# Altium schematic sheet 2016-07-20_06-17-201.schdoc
size 265 x 111 mm; SheetNumber: 1; SheetTotal: 1
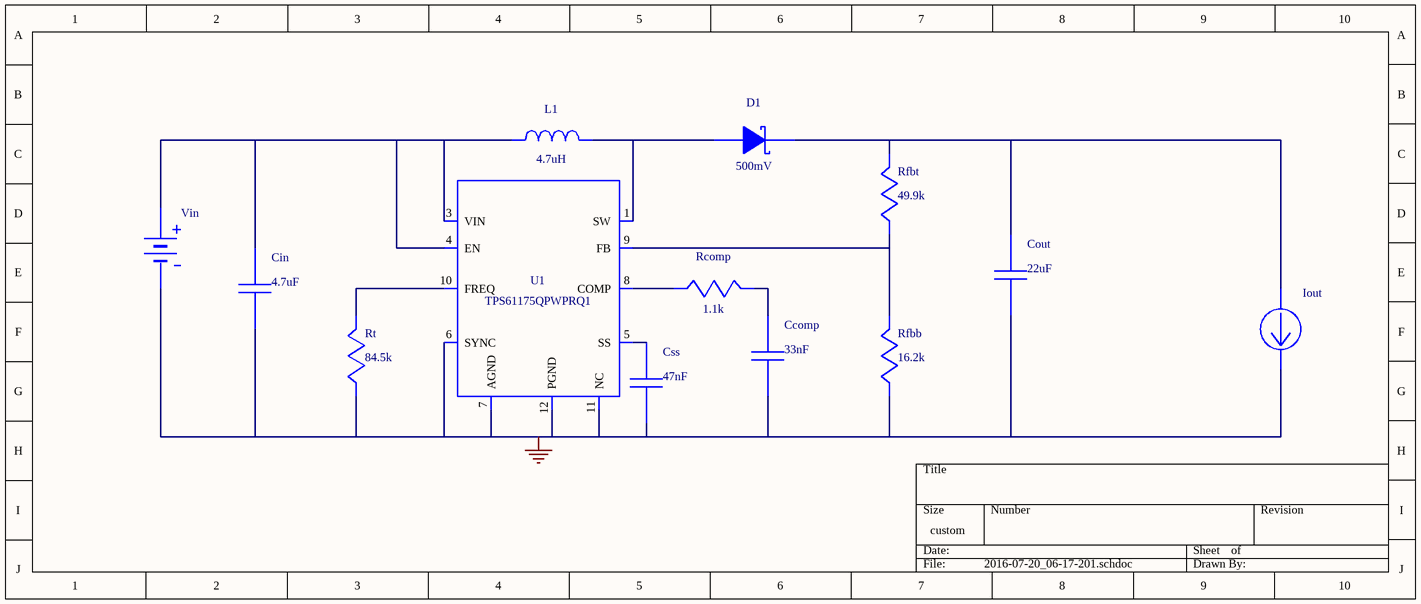
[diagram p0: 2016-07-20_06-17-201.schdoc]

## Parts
Ccomp  value 33nF  (hidden comment: GRM033R60J333KE01D)
Cin  value 4.7uF  (hidden comment: GRM188R60J475KE19D)
Cout  value 22uF  (hidden comment: GRM31CR61A226KE19L)
Css  value 47nF  (hidden comment: TMK212B7473KD-T)
D1  value 500mV  (hidden comment: B340A-13-F)
Iout  WB_CURRENT_LOAD  (value not drawn)
L1  value 4.7uH  (hidden comment: XFL4020-472MEB)
Rcomp  value 1.1k  (hidden comment: CRCW04021K10FKED)
Rfbb  value 16.2k  (hidden comment: CRCW040216K2FKED)
Rfbt  value 49.9k  (hidden comment: CRCW040249K9FKED)
Rt  value 84.5k  (hidden comment: CRCW040284K5FKED)
U1  TPS61175PWP  (value not drawn)
Vin  WB_BATTERY  (value not drawn)

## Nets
0: Ccomp.2 Cin.2 Cout.2 Css.2 Iout.2(-) Rfbb.2 Rt.2 U1.6(SYNC) U1.7(AGND) U1.11(NC) U1.12(PGND) U1.13(PGND) U1.14(PGND) U1.15(EPAD) Vin.2(-)
NetCcomp_1: Ccomp.1 Rcomp.1
NetCin_1: Cin.1 L1.2 U1.3(VIN) U1.4(EN) Vin.1(+)
NetCout_1: Cout.1 D1.1(K) Iout.1(+) Rfbt.1
NetCss_1: Css.1 U1.5(SS)
NetD1_2: D1.2(A) L1.1 U1.1(SW) U1.2(SW)
NetRcomp_2: Rcomp.2 U1.8(COMP)
NetRfbb_1: Rfbb.1 Rfbt.2 U1.9(FB)
NetRt_1: Rt.1 U1.10(FREQ)

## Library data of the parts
Ccomp = GRM033R60J333KE01D: GRM033R60J333KE0; Manufacturer Name: MuRata
Cin = GRM188R60J475KE19D: GRM188R60J475KE1; Manufacturer Name: MuRata
Cout = GRM31CR61A226KE19L: GRM31CR61A226KE1; Manufacturer Name: MuRata
Css = TMK212B7473KD-T: Manufacturer Name: Taiyo Yuden
D1 = B340A-13-F: Manufacturer Name: Diodes Inc.
L1 = XFL4020-472MEB: Manufacturer Name: Coilcraft
Rcomp = CRCW04021K10FKED: Manufacturer Name: Vishay-Dale
Rfbb = CRCW040216K2FKED: Manufacturer Name: Vishay-Dale
Rfbt = CRCW040249K9FKED: Manufacturer Name: Vishay-Dale
Rt = CRCW040284K5FKED: Manufacturer Name: Vishay-Dale
U1 = TPS61175PWP: TPS61175QPWPRQ1; Manufacturer Name: Texas Instruments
